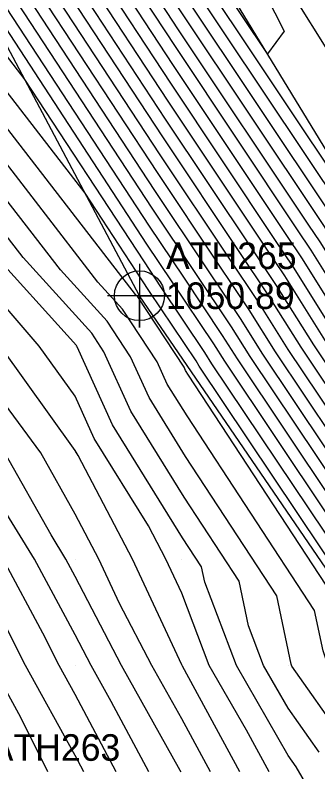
# Model space of a CAD drawing. Extents: x 1213164 to 1213550, y 766120 to 766870.
# Drawn here: x 1213354.4 to 1213382.8, y 766180 to 766251.1 of the extents above; entities that cross this region are included whole.
import ezdxf

# ---------------------------------------------------------------- set-up
doc = ezdxf.new("R2010")
doc.units = 0
for name, color, linetype in [('Default', 7, 'Continuous'), ('Exist DTM Breakline', 7, 'Continuous'), ('Exist DTM Breakline Cogo Elevation', 7, 'Continuous'), ('Exist DTM Breakline Cogo Number', 7, 'Continuous'), ('Exist DTM Breakline Cogo Point CELL', 7, 'Continuous'), ('Exist DTM QL2 LIDAR Elevation Point', 7, 'Continuous'), ('Exist DTM Regular Point Cogo Number', 7, 'Continuous'), ('Exist Roads EOP', 7, 'Continuous')]:
    doc.layers.add(name, color=color, linetype=linetype)

msp = doc.modelspace()

# ---------------------------------------------------------------- linework, layer by layer
at = {"layer": 'Default'}
for points in [[(1213427.023, 766169.166), (1213422.125, 766170.872), (1213409.81, 766193.378), (1213408.211, 766196.08), (1213407.902, 766196.602), (1213393.248, 766219.971), (1213391.952, 766221.907), (1213385.488, 766232.222), (1213385.155, 766232.721), (1213370.451, 766254.787), (1213368.429, 766257.877), (1213362.354, 766267.003), (1213359.462, 766271.426), (1213346.856, 766292.251), (1213345.543, 766294.236), (1213345.467, 766294.362), (1213332.573, 766313.729), (1213328.14, 766319.034), (1213322.727, 766327.122), (1213319.876, 766330.458), (1213316.456, 766335.036), (1213305.271, 766349.172), (1213304.23, 766350.488), (1213296.832, 766356.3)], [(1213425.782, 766168.765), (1213421.234, 766170.35), (1213409.798, 766191.25), (1213407.24, 766195.572), (1213406.745, 766196.408), (1213392.925, 766218.445), (1213390.757, 766221.686), (1213384.656, 766231.421), (1213384.085, 766232.275), (1213370.204, 766253.108), (1213367.367, 766257.443), (1213361.685, 766265.978), (1213357.813, 766271.901), (1213346.177, 766291.124), (1213344.448, 766293.737), (1213344.378, 766293.851), (1213332.558, 766311.606), (1213326.86, 766318.425), (1213322.031, 766325.64), (1213318.4, 766329.889), (1213314.045, 766335.717), (1213304.748, 766347.469), (1213303.882, 766348.563), (1213294.857, 766355.653)], [(1213424.542, 766168.365), (1213420.343, 766169.827), (1213409.786, 766189.122), (1213406.268, 766195.064), (1213405.587, 766196.214), (1213392.603, 766216.92), (1213389.563, 766221.465), (1213383.824, 766230.621), (1213383.016, 766231.83), (1213369.956, 766251.43), (1213366.304, 766257.009), (1213361.016, 766264.954), (1213356.163, 766272.376), (1213345.498, 766289.996), (1213343.353, 766293.237), (1213343.29, 766293.341), (1213332.543, 766309.484), (1213325.58, 766317.816), (1213321.335, 766324.159), (1213316.925, 766329.319), (1213311.635, 766336.399), (1213304.224, 766345.766), (1213303.534, 766346.638), (1213292.883, 766355.006)], [(1213422.061, 766167.563), (1213418.561, 766168.782), (1213409.761, 766184.865), (1213404.325, 766194.049), (1213403.273, 766195.826), (1213391.958, 766213.869), (1213387.173, 766221.022), (1213382.16, 766229.021), (1213380.877, 766230.94), (1213369.461, 766248.073), (1213364.18, 766256.142), (1213359.678, 766262.904), (1213352.865, 766273.326), (1213344.139, 766287.741), (1213341.163, 766292.238), (1213341.113, 766292.321), (1213332.513, 766305.238), (1213323.02, 766316.598), (1213319.942, 766321.196), (1213313.974, 766328.18), (1213306.814, 766337.762), (1213303.177, 766342.36), (1213302.838, 766342.788), (1213288.933, 766353.712)], [(1213423.302, 766167.964), (1213419.452, 766169.305), (1213409.774, 766186.993), (1213405.296, 766194.557), (1213404.43, 766196.02), (1213392.281, 766215.394), (1213388.368, 766221.243), (1213382.992, 766229.821), (1213381.946, 766231.385), (1213369.708, 766249.751), (1213365.242, 766256.575), (1213360.347, 766263.929), (1213354.514, 766272.851), (1213344.818, 766288.869), (1213342.258, 766292.737), (1213342.201, 766292.831), (1213332.528, 766307.361), (1213324.3, 766317.207), (1213320.638, 766322.678), (1213315.449, 766328.75), (1213309.224, 766337.08), (1213303.7, 766344.063), (1213303.186, 766344.713), (1213290.908, 766354.359)], [(1213420.821, 766167.162), (1213417.67, 766168.26), (1213409.749, 766182.737), (1213403.353, 766193.541), (1213402.116, 766195.632), (1213391.636, 766212.343), (1213385.979, 766220.8), (1213381.328, 766228.221), (1213379.808, 766230.495), (1213369.213, 766246.395), (1213363.118, 766255.708), (1213359.009, 766261.879), (1213351.215, 766273.801), (1213343.459, 766286.614), (1213340.068, 766291.738), (1213340.024, 766291.811), (1213332.498, 766303.115), (1213321.74, 766315.988), (1213319.246, 766319.715), (1213312.498, 766327.611), (1213304.404, 766338.444), (1213302.653, 766340.656), (1213302.49, 766340.863), (1213286.958, 766353.065)], [(1213419.58, 766166.762), (1213416.779, 766167.737), (1213409.737, 766180.608), (1213402.382, 766193.033), (1213400.958, 766195.438), (1213391.314, 766210.818), (1213384.784, 766220.579), (1213380.496, 766227.42), (1213378.738, 766230.049), (1213368.965, 766244.716), (1213362.056, 766255.274), (1213358.341, 766260.855), (1213349.566, 766274.276), (1213342.78, 766285.486), (1213338.973, 766291.238), (1213338.935, 766291.301), (1213332.483, 766300.993), (1213320.46, 766315.379), (1213318.549, 766318.234), (1213311.022, 766327.041), (1213302.387, 766338.598), (1213302.066, 766338.953), (1213301.812, 766339.197), (1213284.983, 766352.418)], [(1213418.34, 766166.361), (1213415.888, 766167.215), (1213409.724, 766178.48), (1213401.41, 766192.526), (1213399.801, 766195.243), (1213390.991, 766209.292), (1213383.589, 766220.357), (1213379.664, 766226.62), (1213377.669, 766229.604), (1213368.718, 766243.038), (1213360.993, 766254.84), (1213357.672, 766259.83), (1213347.916, 766274.751), (1213342.101, 766284.359), (1213337.878, 766290.739), (1213337.847, 766290.791), (1213332.468, 766298.87), (1213319.18, 766314.77), (1213317.853, 766316.752), (1213309.547, 766326.472), (1213305.447, 766331.959), (1213300.664, 766337.246), (1213296.875, 766340.877)], [(1213415.859, 766165.56), (1213414.106, 766166.17), (1213409.7, 766174.223), (1213399.467, 766191.51), (1213397.487, 766194.855), (1213390.347, 766206.241), (1213381.2, 766219.915), (1213378, 766225.02), (1213375.53, 766228.714), (1213368.222, 766239.681), (1213358.869, 766253.972), (1213356.334, 766257.78), (1213344.618, 766275.701), (1213340.742, 766282.104), (1213335.689, 766289.739), (1213335.67, 766289.77), (1213332.438, 766294.624), (1213316.619, 766313.552), (1213316.461, 766313.79), (1213314.667, 766315.888), (1213308.633, 766322.211), (1213307.01, 766323.619), (1213305.353, 766325.548), (1213297.859, 766333.832)], [(1213412.138, 766164.357), (1213411.433, 766164.603), (1213409.663, 766167.839), (1213396.552, 766189.987), (1213394.015, 766194.273), (1213389.38, 766201.665), (1213377.616, 766219.25), (1213375.505, 766222.619), (1213372.322, 766227.378), (1213367.479, 766234.646), (1213355.682, 766252.671), (1213354.327, 766254.706), (1213339.67, 766277.126), (1213338.704, 766278.721), (1213332.404, 766288.24), (1213332.404, 766288.24), (1213332.393, 766288.256), (1213332.334, 766288.327), (1213318.129, 766301.733), (1213313.493, 766307.455), (1213311.088, 766310.588), (1213309.781, 766311.957), (1213303.716, 766317.22), (1213297.526, 766324.429)], [(1213398.302, 766167.273), (1213391.311, 766182.637), (1213389.385, 766185.967), (1213387.683, 766188.383), (1213386.252, 766192.632), (1213386.005, 766193.808), (1213370.637, 766217.273), (1213370.354, 766217.731), (1213370.211, 766218.048), (1213365.866, 766224.633), (1213365.644, 766224.878), (1213351.286, 766243.455), (1213348.011, 766247.447), (1213344.739, 766250.464), (1213339.508, 766256.882), (1213332.176, 766264.77), (1213330, 766266.585), (1213326.141, 766270), (1213320, 766275.819), (1213315.808, 766280), (1213310, 766288.059), (1213308.8, 766290), (1213300, 766299.975)], [(1213413.378, 766164.758), (1213412.324, 766165.125), (1213409.675, 766169.967), (1213397.523, 766190.495), (1213395.172, 766194.467), (1213389.702, 766203.19), (1213378.81, 766219.472), (1213376.336, 766223.419), (1213373.391, 766227.824), (1213367.727, 766236.324), (1213356.745, 766253.105), (1213354.996, 766255.731), (1213341.319, 766276.651), (1213339.383, 766279.849), (1213333.499, 766288.74), (1213333.492, 766288.75), (1213332.408, 766290.379), (1213326.445, 766297.514)], [(1213406.02, 766158.464), (1213404.75, 766161.749), (1213403.991, 766165.405), (1213397.264, 766180.187), (1213392.665, 766187.956), (1213389.386, 766193.496), (1213388.09, 766195.563), (1213372.837, 766218.365), (1213372.177, 766219.418), (1213368.044, 766225.598), (1213366.489, 766227.932), (1213355.2, 766245.181), (1213351.863, 766249.498), (1213351.151, 766250.366), (1213350.44, 766251.022), (1213338.916, 766265.161), (1213334.514, 766269.897), (1213332.057, 766271.947), (1213324.144, 766279.448), (1213322.274, 766281.511), (1213320, 766284.171), (1213315.656, 766290), (1213310, 766297.408)], [(1213410.897, 766163.957), (1213410.542, 766164.08), (1213409.65, 766165.71), (1213395.58, 766189.479), (1213392.858, 766194.079), (1213389.057, 766200.139), (1213376.421, 766219.029), (1213374.673, 766221.819), (1213371.253, 766226.933), (1213367.232, 766232.967), (1213354.62, 766252.237), (1213353.659, 766253.682), (1213338.052, 766277.552), (1213338.029, 766277.581), (1213338.022, 766277.587), (1213338.019, 766277.59), (1213338.008, 766277.601), (1213329.882, 766286.567), (1213327.91, 766288.874), (1213318.81, 766297.461)], [(1213390.862, 766178.307), (1213387.226, 766184.594), (1213384.013, 766189.155), (1213383.265, 766191.375), (1213382.468, 766195.177), (1213370.497, 766213.456), (1213368.64, 766216.451), (1213367.706, 766218.527), (1213364.427, 766223.497), (1213362.131, 766226.028), (1213350.997, 766240.434), (1213346.441, 766245.987), (1213341.888, 766250.185), (1213339.804, 766252.742), (1213331.006, 766262.206), (1213330, 766263.046), (1213322.142, 766270), (1213320, 766272.029), (1213312.007, 766280), (1213310, 766282.786), (1213305.54, 766290), (1213300, 766296.279)], [(1213417.099, 766165.96), (1213414.997, 766166.693), (1213409.712, 766176.352), (1213400.438, 766192.018), (1213398.644, 766195.049), (1213390.669, 766207.767), (1213382.394, 766220.136), (1213378.832, 766225.82), (1213376.599, 766229.159), (1213368.47, 766241.359), (1213359.931, 766254.406), (1213357.003, 766258.805), (1213346.267, 766275.226), (1213341.421, 766283.231), (1213336.783, 766290.239), (1213336.758, 766290.281), (1213332.453, 766296.747)], [(1213357.329, 766296.066), (1213358.22, 766290.923), (1213360.922, 766284.555), (1213371.83, 766265.622), (1213372.543, 766263.543), (1213379.601, 766249.625), (1213378.052, 766247.48), (1213370.947, 766258.143), (1213370.553, 766258.744), (1213363.691, 766269.053), (1213362.761, 766270.476), (1213348.215, 766294.507)], [(1213407.843, 766161.026), (1213407.212, 766162.657), (1213406.836, 766164.47), (1213403.498, 766171.806), (1213393.637, 766188.464), (1213390.543, 766193.69), (1213388.413, 766197.088), (1213374.031, 766218.586), (1213373.009, 766220.218), (1213369.114, 766226.043), (1213366.736, 766229.611), (1213352.496, 766251.369), (1213352.321, 766251.632), (1213349.484, 766255.972), (1213338.62, 766269.301), (1213335.684, 766272.46), (1213334.044, 766273.828), (1213328.765, 766278.832), (1213324.81, 766283.196), (1213320, 766288.821), (1213319.121, 766290), (1213316.285, 766293.715)], [(1213386.224, 766233.166), (1213370.699, 766256.465), (1213369.491, 766258.311), (1213363.022, 766268.028), (1213361.111, 766270.951), (1213347.536, 766293.379)], [(1213390.412, 766173.977), (1213385.067, 766183.221), (1213380.343, 766189.928), (1213380.279, 766190.117), (1213378.931, 766196.545), (1213370.356, 766209.638), (1213366.926, 766215.172), (1213365.202, 766219.006), (1213362.988, 766222.36), (1213358.618, 766227.178), (1213350.708, 766237.412), (1213344.871, 766244.528), (1213340, 766249.019), (1213338.96, 766250), (1213330, 766259.543), (1213329.52, 766260), (1213320, 766268.56), (1213318.317, 766270), (1213310, 766278.295), (1213308.789, 766279.733), (1213308.647, 766280), (1213305.97, 766284.03), (1213302.279, 766290), (1213300, 766292.583)], [(1213401.147, 766166.339), (1213391.76, 766186.967), (1213391.544, 766187.34), (1213391.354, 766187.61), (1213391.031, 766188.569), (1213388.229, 766193.302), (1213387.768, 766194.037), (1213371.642, 766218.143), (1213371.345, 766218.618), (1213366.975, 766225.153), (1213366.241, 766226.254), (1213360.916, 766234.391), (1213351.575, 766246.477), (1213349.581, 766248.906), (1213347.589, 766250.743), (1213339.212, 766261.022), (1213333.345, 766267.333), (1213330.07, 766270.066), (1213327.457, 766272.543), (1213320, 766279.609), (1213319.608, 766280), (1213318.596, 766281.404), (1213312.19, 766290), (1213310, 766292.869)], [(1213409.657, 766163.556), (1213409.651, 766163.558), (1213409.638, 766163.582), (1213394.609, 766188.972), (1213391.701, 766193.885), (1213388.735, 766198.614), (1213375.226, 766218.808), (1213373.841, 766221.018), (1213370.183, 766226.488), (1213366.984, 766231.289), (1213353.558, 766251.803), (1213352.99, 766252.657), (1213343.768, 766266.762), (1213338.325, 766273.441), (1213336.853, 766275.024), (1213336.032, 766275.709), (1213333.386, 766278.217), (1213327.346, 766284.882), (1213323.381, 766289.519), (1213319.491, 766293.189)], [(1213414.618, 766165.159), (1213413.215, 766165.648), (1213409.687, 766172.095), (1213398.495, 766191.003), (1213396.329, 766194.661), (1213390.024, 766204.716), (1213380.005, 766219.693), (1213377.168, 766224.219), (1213374.461, 766228.269), (1213367.975, 766238.003), (1213357.807, 766253.539), (1213355.665, 766256.756), (1213342.968, 766276.176), (1213340.063, 766280.976), (1213334.594, 766289.239), (1213334.581, 766289.26), (1213332.423, 766292.502)], [(1213382.907, 766181.848), (1213380, 766185.976), (1213377.686, 766190), (1213376.271, 766193.729), (1213375.394, 766197.913), (1213370.215, 766205.821), (1213365.212, 766213.892), (1213362.697, 766219.484), (1213361.55, 766221.224), (1213355.105, 766228.329), (1213350.42, 766234.391), (1213343.301, 766243.069), (1213340, 766246.112), (1213335.881, 766250), (1213330, 766256.264), (1213326.072, 766260), (1213320, 766265.46), (1213314.693, 766270), (1213310, 766274.68), (1213306.222, 766279.168), (1213305.779, 766280), (1213300, 766288.7), (1213299.426, 766289.426), (1213298.823, 766290)], [(1213382.426, 766177.574), (1213380.748, 766180.476), (1213380, 766181.538), (1213375.134, 766190), (1213372.158, 766197.842), (1213371.856, 766199.282), (1213370.074, 766202.003), (1213363.498, 766212.612), (1213360.193, 766219.963), (1213360.111, 766220.088), (1213351.592, 766229.479), (1213350.131, 766231.369), (1213341.731, 766241.609), (1213340, 766243.205), (1213332.802, 766250), (1213330, 766252.985), (1213322.625, 766260), (1213320, 766262.36), (1213311.069, 766270), (1213310, 766271.066), (1213303.654, 766278.603), (1213302.911, 766280), (1213300, 766284.383), (1213297.518, 766287.518)], [(1213375.448, 766180), (1213370.07, 766189.93), (1213370.03, 766190), (1213370, 766190.078), (1213365.361, 766200), (1213360.272, 766209.728), (1213360.071, 766210.053), (1213360, 766210.21), (1213352.969, 766220), (1213350, 766223.443), (1213344.895, 766230), (1213340, 766236.23), (1213336.75, 766240), (1213330, 766246.311), (1213326.179, 766250), (1213320, 766255.873), (1213315.679, 766260), (1213310, 766264.885), (1213304.642, 766270), (1213300.643, 766274.799), (1213299.076, 766276.583), (1213297.321, 766278.701)], [(1213372.694, 766180), (1213370, 766184.975), (1213367.184, 766190), (1213364.163, 766195.837), (1213362.216, 766200), (1213360, 766204.237), (1213356.762, 766210), (1213350, 766219.142), (1213349.403, 766220), (1213347.2, 766222.8), (1213341.594, 766230), (1213340, 766232.029), (1213333.13, 766240), (1213330, 766242.926), (1213322.674, 766250), (1213320, 766252.541), (1213312.191, 766260), (1213310, 766261.884), (1213301.499, 766270), (1213300.208, 766271.55), (1213297.067, 766275.126)], [(1213363.857, 766180), (1213360, 766187.265), (1213358.494, 766190), (1213356.952, 766193.048), (1213353.22, 766200), (1213350, 766205.222), (1213346.909, 766210), (1213340, 766219.818), (1213339.895, 766219.942), (1213339.88, 766220), (1213339.57, 766220.43), (1213332.681, 766230), (1213330, 766233.015), (1213322.591, 766240), (1213320, 766242.503), (1213312.179, 766250), (1213310, 766252.081), (1213301.814, 766260), (1213300, 766261.724), (1213291.701, 766270)], [(1213366.896, 766180), (1213363.383, 766186.617), (1213361.487, 766190), (1213360, 766192.873), (1213356.174, 766200), (1213350.02, 766209.98), (1213350.009, 766210), (1213350, 766210.012), (1213343.047, 766220), (1213340, 766223.872), (1213335.589, 766230), (1213330, 766236.286), (1213326.061, 766240), (1213320, 766245.854), (1213315.675, 766250), (1213310, 766255.42), (1213305.265, 766260), (1213300, 766265.004), (1213294.99, 766270)], [(1213369.935, 766180), (1213369.861, 766180.139), (1213364.336, 766190), (1213360, 766198.376), (1213359.128, 766200), (1213357.725, 766202.275), (1213353.386, 766210), (1213350, 766214.577), (1213346.225, 766220), (1213340, 766227.912), (1213338.497, 766230), (1213330, 766239.557), (1213329.53, 766240), (1213320, 766249.205), (1213319.17, 766250), (1213310, 766258.758), (1213308.717, 766260), (1213300, 766268.285), (1213298.28, 766270)], [(1213357.412, 766180), (1213354.875, 766185.125), (1213352.19, 766190), (1213350, 766194.33), (1213346.999, 766200), (1213342.014, 766207.986), (1213340.711, 766210), (1213340, 766211.011), (1213334.833, 766217.144), (1213334.09, 766220), (1213330, 766225.672), (1213326.483, 766230), (1213320, 766236.133), (1213315.41, 766240), (1213310, 766245.176), (1213308.476, 766245.971), (1213304.999, 766250), (1213300, 766254.828), (1213294.718, 766260)], [(1213360.819, 766180), (1213360, 766181.542), (1213355.342, 766190), (1213350.574, 766199.426), (1213350.266, 766200), (1213350, 766200.431), (1213343.81, 766210), (1213340, 766215.414), (1213337.364, 766218.543), (1213336.985, 766220), (1213330, 766229.687), (1213329.746, 766230), (1213320, 766239.219), (1213319.073, 766240), (1213310, 766248.68), (1213309.583, 766248.898), (1213308.632, 766250), (1213300, 766258.336), (1213298.301, 766260)], [(1213378.201, 766180), (1213376.075, 766183.925), (1213372.582, 766190), (1213370, 766196.804), (1213368.506, 766200), (1213366.866, 766203.134), (1213361.784, 766211.332), (1213360, 766215.301), (1213356.625, 766220), (1213350, 766227.682), (1213348.195, 766230), (1213341.579, 766238.421), (1213340.161, 766240.15), (1213340, 766240.298), (1213334.673, 766245.327), (1213330, 766249.696), (1213329.685, 766250), (1213320, 766259.205)]]:
    msp.add_lwpolyline(points, dxfattribs=at)
at = {"layer": 'Exist DTM Breakline'}
for points in [[(1213422.776, 766171.254), (1213409.831, 766196.926), (1213386.657, 766233.346), (1213364.326, 766270.025), (1213348.91, 766295.975), (1213348.91, 766295.975), (1213325.275, 766332.542), (1213305.812, 766359.242), (1213281.253, 766381.475), (1213256.992, 766395.586), (1213227.813, 766408.558), (1213197.433, 766416.071)], [(1213409.638, 766163.55), (1213387.59, 766193.195), (1213366.02, 766224.755), (1213332.393, 766288.235), (1213308.213, 766325.957), (1213302.167, 766339.076)]]:
    msp.add_lwpolyline(points, dxfattribs=at)
at = {"layer": 'Exist DTM Breakline Cogo Point CELL'}
msp.add_lwpolyline([(1213366.02, 766227.755), (1213366.02, 766221.755), (1213366.02, 766224.755), (1213369.02, 766224.755), (1213363.02, 766224.755)], dxfattribs=at)
msp.add_circle((1213366.02, 766224.755), 2.344, dxfattribs=at)
at = {"layer": 'Exist DTM QL2 LIDAR Elevation Point'}
for p, q in [((1213360, 766220), (1213360, 766220)), ((1213360, 766210), (1213360, 766210)), ((1213360, 766200), (1213360, 766200)), ((1213370, 766200), (1213370, 766200)), ((1213360, 766190), (1213360, 766190)), ((1213370, 766190), (1213370, 766190)), ((1213380, 766190), (1213380, 766190))]:
    msp.add_line(p, q, dxfattribs=at)
at = {"layer": 'Exist Roads EOP'}
msp.add_lwpolyline([(1213357.309, 766290.426), (1213372.992, 766264.94), (1213391.284, 766235.628), (1213411.809, 766200.385)], dxfattribs=at)

# ---------------------------------------------------------------- texts
at = {"layer": 'Exist DTM Breakline Cogo Elevation'}
msp.add_text('1050.89', height=2.5, dxfattribs=at).set_placement((1213368.52, 766223.505))
at = {"layer": 'Exist DTM Breakline Cogo Number'}
msp.add_text('ATH265', height=2.5, dxfattribs=at).set_placement((1213368.52, 766227.255))
at = {"layer": 'Exist DTM Regular Point Cogo Number'}
msp.add_text('ATH263', height=2.5, dxfattribs=at).set_placement((1213351.965, 766181.042))

doc.saveas('drawing.dxf')
